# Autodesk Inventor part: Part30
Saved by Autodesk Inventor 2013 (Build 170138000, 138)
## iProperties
Created: 2012-07
Part Number: Part30
Material: Acetal Resin, Black
Document SubType Name: Modeling
Designer: Paul
Density: 1 g/cm^3
Author: Paul
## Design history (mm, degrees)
node "User Library-Arduino Mega.SAT1"
body "Solid1"
node "Base1"
